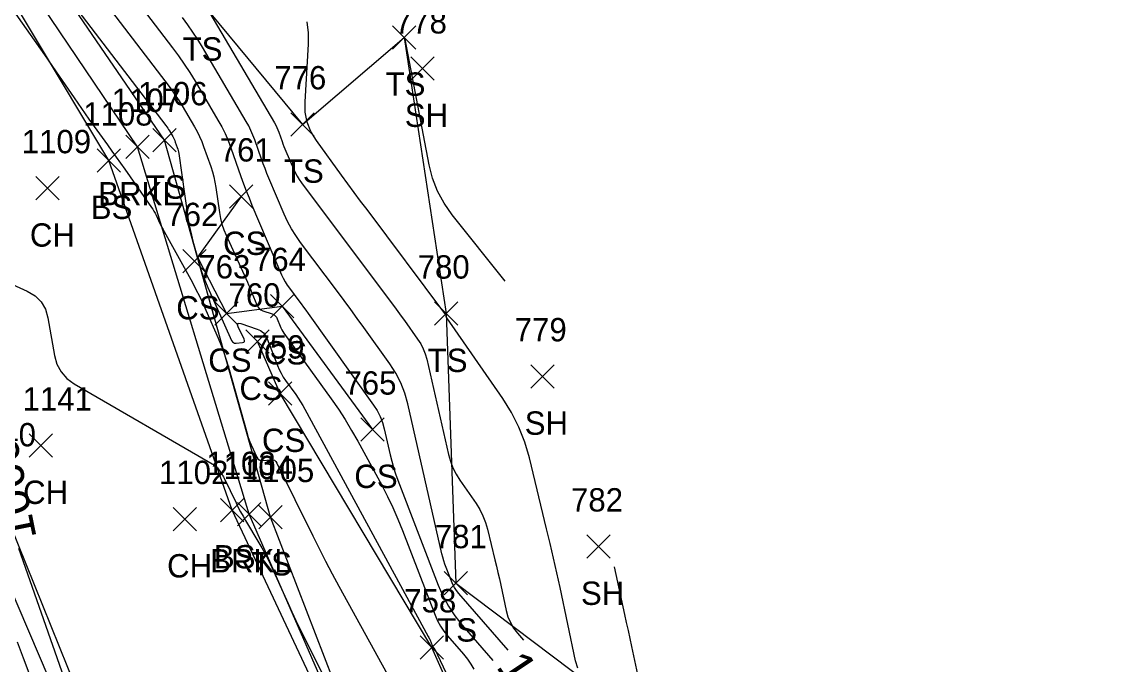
# Model space of a CAD drawing. Extents: x 1592612 to 1596497, y 111838 to 113741.
# Drawn here: x 1592792 to 1592886.6, y 113612.1 to 113667.2 of the extents above; entities that cross this region are included whole.
import ezdxf

# ---------------------------------------------------------------- set-up
doc = ezdxf.new("R2010")
doc.units = 0
for name, color, linetype in [('L_A', 7, 'Continuous'), ('L_I', 7, 'Continuous'), ('L_TIC', 7, 'Continuous'), ('LAWE', 7, 'Continuous'), ('LELB', 7, 'Continuous'), ('LSOGCMA', 7, 'Continuous'), ('LSOGCMA_T', 7, 'Continuous'), ('LSOGCMI', 7, 'Continuous')]:
    doc.layers.add(name, color=color, linetype=linetype)

msp = doc.modelspace()

# ---------------------------------------------------------------- linework, layer by layer
at = {"layer": 'L_TIC'}
for points in [[(1592823.781, 113664.882), (1592825.781, 113666.882)], [(1592825.781, 113664.882), (1592823.781, 113666.882)], [(1592825.347, 113662.217), (1592827.347, 113664.217)], [(1592827.347, 113662.217), (1592825.347, 113664.217)], [(1592815.061, 113657.432), (1592817.061, 113659.432)], [(1592817.061, 113657.432), (1592815.061, 113659.432)], [(1592803.231, 113656.067), (1592805.231, 113658.067)], [(1592805.231, 113656.067), (1592803.231, 113658.067)], [(1592800.909, 113655.496), (1592802.909, 113657.496)], [(1592802.909, 113655.496), (1592800.909, 113657.496)], [(1592798.469, 113654.332), (1592800.469, 113656.332)], [(1592800.469, 113654.332), (1592798.469, 113656.332)], [(1592793.204, 113651.957), (1592795.204, 113653.957)], [(1592795.204, 113651.957), (1592793.204, 113653.957)], [(1592809.816, 113651.25), (1592811.816, 113653.25)], [(1592811.816, 113651.25), (1592809.816, 113653.25)], [(1592805.801, 113645.721), (1592807.801, 113647.721)], [(1592807.801, 113645.721), (1592805.801, 113647.721)], [(1592813.311, 113641.864), (1592815.311, 113643.864)], [(1592815.311, 113641.864), (1592813.311, 113643.864)], [(1592808.543, 113641.233), (1592810.543, 113643.233)], [(1592810.543, 113641.233), (1592808.543, 113643.233)], [(1592827.389, 113641.22), (1592829.389, 113643.22)], [(1592829.389, 113641.22), (1592827.389, 113643.22)], [(1592811.219, 113638.821), (1592813.219, 113640.821)], [(1592813.219, 113638.821), (1592811.219, 113640.821)], [(1592835.631, 113635.845), (1592837.631, 113637.845)], [(1592837.631, 113635.845), (1592835.631, 113637.845)], [(1592813.15, 113634.371), (1592815.15, 113636.371)], [(1592815.15, 113634.371), (1592813.15, 113636.371)], [(1592821.069, 113631.281), (1592823.069, 113633.281)], [(1592823.069, 113631.281), (1592821.069, 113633.281)], [(1592792.623, 113629.917), (1592794.623, 113631.917)], [(1592794.623, 113629.917), (1592792.623, 113631.917)], [(1592804.968, 113623.618), (1592806.968, 113625.618)], [(1592806.968, 113623.618), (1592804.968, 113625.618)], [(1592809.027, 113624.391), (1592811.027, 113626.391)], [(1592811.027, 113624.391), (1592809.027, 113626.391)], [(1592810.502, 113624.047), (1592812.502, 113626.047)], [(1592812.502, 113624.047), (1592810.502, 113626.047)], [(1592812.329, 113623.79), (1592814.329, 113625.79)], [(1592814.329, 113623.79), (1592812.329, 113625.79)], [(1592840.452, 113621.268), (1592842.452, 113623.268)], [(1592842.452, 113621.268), (1592840.452, 113623.268)], [(1592828.203, 113618.126), (1592830.203, 113620.126)], [(1592830.203, 113618.126), (1592828.203, 113620.126)], [(1592826.152, 113612.626), (1592828.152, 113614.626)], [(1592828.152, 113612.626), (1592826.152, 113614.626)]]:
    msp.add_lwpolyline(points, dxfattribs=at)
at = {"layer": 'LAWE'}
for points in [[(1592886.537, 113460.922), (1592877.744, 113481.574), (1592863.095, 113501.144), (1592852.902, 113518.209), (1592848.805, 113541.382), (1592835.879, 113571.623), (1592826.212, 113589.998), (1592821.08, 113603.103), (1592811.502, 113625.047), (1592801.909, 113656.496), (1592787.746, 113677.481), (1592769.551, 113701.793), (1592752.509, 113717.946)], [(1592867.645, 113460.38), (1592859.409, 113477.515), (1592844.793, 113495.549), (1592832.37, 113516.6), (1592826.928, 113530.545), (1592818.762, 113547.936), (1592807.597, 113581.108), (1592797.669, 113603.177), (1592787.513, 113626.88), (1592776.477, 113646.362), (1592766.38, 113665.342), (1592748.736, 113682.085), (1592730.356, 113695.945)]]:
    msp.add_lwpolyline(points, dxfattribs=at)
at = {"layer": 'LELB'}
for points in [[(1592764.358, 113725.461), (1592786.757, 113707.3), (1592794.357, 113706.99), (1592806.432, 113680.654), (1592807.376, 113668.893), (1592816.061, 113658.432), (1592824.781, 113665.882), (1592828.389, 113642.22), (1592829.203, 113619.126), (1592847.35, 113605.446), (1592857.769, 113601.143), (1592858.44, 113592.421), (1592865.761, 113577.691)], [(1592886.583, 113460.952), (1592879.778, 113482.315), (1592863.966, 113501.755), (1592853.366, 113518.29), (1592851.192, 113542.037), (1592841.019, 113567.093), (1592831.516, 113591.894), (1592821.816, 113602.808), (1592813.329, 113624.79), (1592804.232, 113657.067), (1592789.644, 113678.369), (1592770.935, 113703.549), (1592752.623, 113718.428)], [(1592886.43, 113460.851), (1592879.543, 113465.926), (1592876.137, 113481.194), (1592862.304, 113500.643), (1592852.529, 113517.932), (1592848.162, 113540.894), (1592835.177, 113571.255), (1592825.196, 113589.927), (1592820.421, 113603.303), (1592810.027, 113625.391), (1592799.468, 113655.332), (1592786.607, 113676.744), (1592768.899, 113700.806), (1592752.213, 113717.027)], [(1592869.098, 113460.398), (1592860.441, 113478.115), (1592844.631, 113496.556), (1592834.165, 113516.964), (1592828.396, 113531.171), (1592823.559, 113549.918), (1592808.456, 113581.723), (1592799.527, 113603.061), (1592789.48, 113627.849), (1592777.21, 113647.427), (1592766.461, 113666.146), (1592749.422, 113683.288), (1592730.933, 113697.021)], [(1592810.816, 113652.25), (1592807.055, 113647.069), (1592809.543, 113642.233), (1592814.311, 113642.864), (1592822.069, 113632.281)], [(1592860.223, 113546.827), (1592857.498, 113559.424), (1592844.332, 113573.876), (1592833.529, 113599.277), (1592827.152, 113613.626), (1592814.151, 113635.371), (1592812.219, 113639.821)]]:
    msp.add_lwpolyline(points, dxfattribs=at)
at = {"layer": 'LSOGCMA'}
for points in [[(1592833.702, 113613.384), (1592829.462, 113618.256), (1592829.27, 113618.498), (1592829.1, 113618.754), (1592828.954, 113619.023), (1592828.83, 113619.307), (1592828.384, 113620.468), (1592828.277, 113620.76), (1592828.182, 113621.056), (1592828.096, 113621.354), (1592828.022, 113621.656), (1592825.09, 113634.492), (1592824.833, 113635.407), (1592824.491, 113636.282), (1592824.063, 113637.12), (1592823.549, 113637.918), (1592821.321, 113641.036), (1592820.762, 113641.813), (1592820.198, 113642.587), (1592819.629, 113643.358), (1592819.056, 113644.125), (1592815.899, 113648.326), (1592815.494, 113648.9), (1592815.125, 113649.495), (1592814.794, 113650.111), (1592814.499, 113650.749), (1592813.183, 113653.836), (1592813.016, 113654.238), (1592812.855, 113654.643), (1592812.7, 113655.05), (1592812.553, 113655.46), (1592811.974, 113657.105), (1592811.82, 113657.511), (1592811.647, 113657.909), (1592811.454, 113658.298), (1592811.242, 113658.678), (1592807.484, 113665.05), (1592807.085, 113665.703), (1592806.667, 113666.344), (1592806.23, 113666.972), (1592805.774, 113667.588)], [(1592787.913, 113646.209), (1592792.467, 113644.137), (1592793.135, 113643.741), (1592793.653, 113643.228), (1592794.02, 113642.599), (1592794.237, 113641.853), (1592794.803, 113638.638), (1592795.015, 113637.883), (1592795.369, 113637.227), (1592795.863, 113636.669), (1592796.498, 113636.21), (1592808.508, 113629.238), (1592808.606, 113629.174), (1592808.695, 113629.101), (1592808.776, 113629.018), (1592808.848, 113628.925), (1592809.12, 113628.538), (1592809.186, 113628.44), (1592809.248, 113628.339), (1592809.305, 113628.236), (1592809.358, 113628.13), (1592810.371, 113626.004), (1592810.561, 113625.617), (1592810.762, 113625.235), (1592810.971, 113624.858), (1592811.19, 113624.486), (1592812.335, 113622.597), (1592812.594, 113622.156), (1592812.839, 113621.707), (1592813.07, 113621.252), (1592813.287, 113620.789), (1592814.825, 113617.385), (1592815.155, 113616.664), (1592815.493, 113615.946), (1592815.838, 113615.233), (1592816.191, 113614.522), (1592818.757, 113609.429)], [(1592797.582, 113605.486), (1592791.75, 113622.113)]]:
    msp.add_lwpolyline(points, dxfattribs=at)
at = {"layer": 'LSOGCMI'}
for points in [[(1592793.796, 113675.853), (1592804.635, 113661.669), (1592804.933, 113661.267), (1592805.218, 113660.856), (1592805.492, 113660.437), (1592805.753, 113660.009), (1592806.813, 113658.212), (1592807.037, 113657.811), (1592807.24, 113657.4), (1592807.423, 113656.98), (1592807.586, 113656.55), (1592808.197, 113654.811), (1592808.339, 113654.374), (1592808.459, 113653.932), (1592808.557, 113653.484), (1592808.634, 113653.03), (1592808.941, 113650.887), (1592809.031, 113650.383), (1592809.157, 113649.889), (1592809.318, 113649.405), (1592809.513, 113648.932), (1592811.338, 113644.924), (1592811.442, 113644.694), (1592811.542, 113644.463), (1592811.641, 113644.232), (1592811.736, 113643.999), (1592812.157, 113642.961), (1592812.244, 113642.794), (1592812.36, 113642.658), (1592812.503, 113642.551), (1592812.674, 113642.473), (1592813.463, 113642.206), (1592813.611, 113642.139), (1592813.734, 113642.045), (1592813.832, 113641.926), (1592813.905, 113641.781), (1592814.147, 113641.149), (1592814.212, 113640.993), (1592814.287, 113640.843), (1592814.371, 113640.698), (1592814.465, 113640.558), (1592818.529, 113634.914), (1592819.141, 113634.035), (1592819.725, 113633.137), (1592820.28, 113632.222), (1592820.807, 113631.288), (1592822.856, 113627.519), (1592823.352, 113626.569), (1592823.817, 113625.604), (1592824.249, 113624.625), (1592824.65, 113623.631), (1592827.439, 113616.379), (1592827.646, 113615.903), (1592827.892, 113615.449), (1592828.177, 113615.019), (1592828.501, 113614.613), (1592829.876, 113613.034), (1592830.204, 113612.629), (1592830.503, 113612.205), (1592830.771, 113611.761)], [(1592788.325, 113672.344), (1592793.937, 113664.383), (1592794.257, 113663.927), (1592794.577, 113663.469), (1592794.895, 113663.011), (1592795.211, 113662.552), (1592796.475, 113660.713), (1592796.792, 113660.254), (1592797.112, 113659.797), (1592797.434, 113659.341), (1592797.758, 113658.887), (1592799.348, 113656.671), (1592799.721, 113656.151), (1592800.093, 113655.629), (1592800.463, 113655.106), (1592800.831, 113654.582), (1592803.117, 113651.325), (1592803.226, 113651.163), (1592803.328, 113650.996), (1592803.423, 113650.826), (1592803.51, 113650.652), (1592803.846, 113649.946), (1592803.932, 113649.77), (1592804.02, 113649.595), (1592804.111, 113649.422), (1592804.204, 113649.251), (1592806.624, 113644.877), (1592806.935, 113644.299), (1592807.232, 113643.713), (1592807.515, 113643.121), (1592807.783, 113642.521), (1592808.829, 113640.109), (1592809.08, 113639.502), (1592809.31, 113638.888), (1592809.519, 113638.267), (1592809.708, 113637.638), (1592811.313, 113631.949), (1592811.386, 113631.706), (1592811.468, 113631.466), (1592811.559, 113631.229), (1592811.659, 113630.995), (1592812.138, 113629.93), (1592812.224, 113629.789), (1592812.337, 113629.694), (1592812.476, 113629.643), (1592812.642, 113629.639), (1592813.357, 113629.71), (1592813.523, 113629.706), (1592813.664, 113629.656), (1592813.781, 113629.562), (1592813.873, 113629.424), (1592816.943, 113623.187), (1592817.488, 113622.098), (1592818.044, 113621.014), (1592818.613, 113619.937), (1592819.194, 113618.866), (1592823.667, 113610.731)], [(1592799.068, 113672.658), (1592804.926, 113664.993), (1592805.439, 113664.3), (1592805.931, 113663.592), (1592806.402, 113662.871), (1592806.851, 113662.134), (1592808.817, 113658.802), (1592809.136, 113658.231), (1592809.425, 113657.646), (1592809.686, 113657.048), (1592809.918, 113656.437), (1592810.787, 113653.964), (1592811.009, 113653.348), (1592811.241, 113652.736), (1592811.483, 113652.127), (1592811.735, 113651.523), (1592814.28, 113645.553), (1592814.421, 113645.248), (1592814.579, 113644.953), (1592814.755, 113644.669), (1592814.949, 113644.395), (1592815.758, 113643.318), (1592815.96, 113643.048), (1592816.16, 113642.777), (1592816.358, 113642.505), (1592816.555, 113642.231), (1592822.159, 113634.389), (1592822.465, 113633.915), (1592822.719, 113633.417), (1592822.922, 113632.897), (1592823.075, 113632.354), (1592823.581, 113630.135), (1592823.718, 113629.583), (1592823.874, 113629.037), (1592824.049, 113628.498), (1592824.243, 113627.964), (1592827.707, 113618.955), (1592828.108, 113618.032), (1592828.585, 113617.155), (1592829.137, 113616.323), (1592829.764, 113615.536), (1592832.395, 113612.513)], [(1592795.405, 113670.042), (1592804.343, 113658.346), (1592804.426, 113658.234), (1592804.506, 113658.12), (1592804.582, 113658.003), (1592804.654, 113657.885), (1592804.949, 113657.385), (1592805.011, 113657.274), (1592805.067, 113657.16), (1592805.118, 113657.043), (1592805.163, 113656.923), (1592805.333, 113656.44), (1592805.373, 113656.319), (1592805.406, 113656.196), (1592805.433, 113656.072), (1592805.454, 113655.946), (1592806.24, 113650.462), (1592806.323, 113649.947), (1592806.422, 113649.436), (1592806.538, 113648.928), (1592806.672, 113648.424), (1592807.238, 113646.415), (1592807.389, 113645.916), (1592807.558, 113645.424), (1592807.744, 113644.938), (1592807.949, 113644.459), (1592809.987, 113639.92), (1592810.054, 113639.813), (1592810.14, 113639.74), (1592810.246, 113639.701), (1592810.372, 113639.698), (1592810.918, 113639.752), (1592811.03, 113639.78), (1592811.092, 113639.834), (1592811.106, 113639.916), (1592811.07, 113640.025), (1592810.547, 113641.087), (1592810.481, 113641.268), (1592810.5, 113641.375), (1592810.604, 113641.408), (1592810.792, 113641.367), (1592812.192, 113640.893), (1592812.478, 113640.763), (1592812.715, 113640.583), (1592812.905, 113640.352), (1592813.046, 113640.072), (1592813.923, 113637.777), (1592814.066, 113637.436), (1592814.229, 113637.108), (1592814.414, 113636.79), (1592814.62, 113636.484), (1592815.485, 113635.282), (1592815.697, 113634.978), (1592815.898, 113634.669), (1592816.09, 113634.353), (1592816.272, 113634.031), (1592826.855, 113614.558), (1592826.896, 113614.48), (1592826.935, 113614.4), (1592826.971, 113614.319), (1592827.004, 113614.237), (1592827.17, 113613.804), (1592827.184, 113613.773), (1592827.2, 113613.744), (1592827.218, 113613.716), (1592827.239, 113613.69), (1592827.328, 113613.587), (1592827.349, 113613.561), (1592827.369, 113613.534), (1592827.386, 113613.505), (1592827.401, 113613.475), (1592833.955, 113599.597)], [(1592808.127, 113667.946), (1592813.667, 113658.554), (1592813.773, 113658.365), (1592813.868, 113658.172), (1592813.954, 113657.975), (1592814.031, 113657.773), (1592814.318, 113656.956), (1592814.392, 113656.752), (1592814.468, 113656.55), (1592814.548, 113656.349), (1592814.632, 113656.149), (1592815.285, 113654.615), (1592815.432, 113654.298), (1592815.596, 113653.992), (1592815.779, 113653.697), (1592815.98, 113653.412), (1592823.669, 113643.183), (1592823.959, 113642.795), (1592824.247, 113642.406), (1592824.532, 113642.014), (1592824.815, 113641.621), (1592825.941, 113640.044), (1592826.201, 113639.641), (1592826.418, 113639.217), (1592826.591, 113638.774), (1592826.72, 113638.312), (1592828.584, 113630.153), (1592828.747, 113629.569), (1592828.962, 113629.009), (1592829.231, 113628.471), (1592829.553, 113627.958), (1592830.946, 113625.949), (1592831.269, 113625.436), (1592831.54, 113624.9), (1592831.761, 113624.34), (1592831.931, 113623.758), (1592832.567, 113621.142), (1592832.697, 113620.599), (1592832.823, 113620.055), (1592832.945, 113619.51), (1592833.063, 113618.965), (1592833.529, 113616.781), (1592833.677, 113616.251), (1592833.887, 113615.751), (1592834.16, 113615.283), (1592834.495, 113614.847), (1592835.01, 113614.256)], [(1592839.667, 113611.841), (1592839.488, 113612.484), (1592838.15, 113618.752), (1592837.875, 113620.016), (1592837.592, 113621.278), (1592837.3, 113622.539), (1592836.998, 113623.797), (1592835.525, 113629.86), (1592835.132, 113631.21), (1592834.62, 113632.506), (1592833.99, 113633.75), (1592833.242, 113634.94), (1592828.433, 113641.872), (1592828.418, 113641.897), (1592828.405, 113641.924), (1592828.394, 113641.951), (1592828.386, 113641.979), (1592828.351, 113642.132), (1592828.348, 113642.142), (1592828.344, 113642.152), (1592828.34, 113642.162), (1592828.334, 113642.171), (1592828.308, 113642.206), (1592828.296, 113642.224), (1592828.283, 113642.241), (1592821.598, 113651.134), (1592821.048, 113651.868), (1592820.501, 113652.604), (1592819.958, 113653.343), (1592819.417, 113654.083), (1592817.259, 113657.05), (1592816.794, 113657.813), (1592816.477, 113658.62), (1592816.309, 113659.47), (1592816.29, 113660.364), (1592816.587, 113665.308), (1592816.583, 113666.281), (1592816.453, 113667.227)], [(1592833.45, 113645.002), (1592828.898, 113650.696), (1592828.205, 113651.675), (1592827.646, 113652.716), (1592827.219, 113653.818), (1592826.925, 113654.981), (1592824.874, 113665.723)], [(1592826.35, 113663.208), (1592826.347, 113663.213), (1592826.346, 113663.218)], [(1592842.784, 113620.542), (1592843.68, 113616.432), (1592843.828, 113615.747), (1592843.976, 113615.062), (1592844.124, 113614.377), (1592844.271, 113613.691), (1592845.719, 113606.905)], [(1592790.805, 113596.174), (1592794.712, 113602.201), (1592794.831, 113602.408), (1592794.925, 113602.624), (1592794.995, 113602.849), (1592795.041, 113603.083), (1592795.173, 113604.039), (1592795.192, 113604.276), (1592795.18, 113604.51), (1592795.14, 113604.74), (1592795.069, 113604.967), (1592792.151, 113612.707), (1592791.639, 113614.073)]]:
    msp.add_lwpolyline(points, dxfattribs=at)

# ---------------------------------------------------------------- texts
at = {"layer": 'L_A'}
for s, p in [('TS', (1592805.785, 113663.893)), ('TS', (1592823.19, 113660.882)), ('SH', (1592824.835, 113658.217)), ('TS', (1592814.471, 113653.432)), ('TS', (1592802.641, 113652.067)), ('BRKL', (1592798.554, 113651.496)), ('BS', (1592797.91, 113650.332)), ('CH', (1592792.692, 113647.957)), ('CS', (1592809.257, 113647.25)), ('CS', (1592805.242, 113641.721)), ('CS', (1592812.752, 113637.864)), ('CS', (1592807.984, 113637.233)), ('TS', (1592826.798, 113637.22)), ('CS', (1592810.66, 113634.821)), ('SH', (1592835.119, 113631.845)), ('CS', (1592812.591, 113630.371)), ('CS', (1592820.51, 113627.281)), ('CH', (1592792.111, 113625.917)), ('BRKL', (1592808.148, 113620.047)), ('BS', (1592808.468, 113620.391)), ('TS', (1592811.739, 113619.79)), ('CH', (1592804.456, 113619.618)), ('SH', (1592839.94, 113617.268)), ('TS', (1592827.613, 113614.126))]:
    msp.add_text(s, height=2, dxfattribs=at).set_placement(p)
at = {"layer": 'L_I'}
for s, p in [('778', (1592823.985, 113666.217)), ('776', (1592813.644, 113661.432)), ('1107', (1592799.704, 113659.496)), ('1106', (1592801.972, 113660.067)), ('1108', (1592797.264, 113658.332)), ('1109', (1592791.991, 113655.957)), ('761', (1592808.973, 113655.25)), ('762', (1592804.392, 113649.721)), ('764', (1592811.902, 113645.864)), ('763', (1592807.134, 113645.233)), ('780', (1592825.94, 113645.22)), ('760', (1592809.723, 113642.821)), ('779', (1592834.261, 113639.845)), ('759', (1592811.78, 113638.371)), ('765', (1592819.66, 113635.281)), ('1141', (1592792.064, 113633.917)), ('1140', (1592787.268, 113630.849)), ('1103', (1592807.822, 113628.391)), ('1102', (1592803.763, 113627.618)), ('1104', (1592809.297, 113628.047)), ('1105', (1592811.125, 113627.79)), ('782', (1592839.089, 113625.268)), ('781', (1592827.408, 113622.126)), ('758', (1592824.789, 113616.626))]:
    msp.add_text(s, height=2, dxfattribs=at).set_placement(p)
at = {"layer": 'LSOGCMA_T'}
for s, rotation, p in [('1060', 101.43171, (1592793.28, 113623.033)), ('1070', 303.67341, (1592832.611, 113611.976))]:
    msp.add_text(s, height=3, rotation=rotation, dxfattribs=at).set_placement(p)

doc.saveas('drawing.dxf')
